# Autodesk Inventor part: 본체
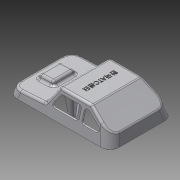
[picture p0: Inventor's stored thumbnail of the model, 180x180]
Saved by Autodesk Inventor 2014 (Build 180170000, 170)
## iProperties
Created: 2015-05
Part Number: 본체
Material: ABS 플라스틱
Document SubType Name: Modeling
Designer: Administrator
Density: 1.06 g/cm^3
Appearance: 매끄러움 - 흰색
Mass: 32.7557 g
Surface Area: 310.511 cm^2
Volume: 30.9016 cm^3
Author: Administrator
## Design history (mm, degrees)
sketch "스케치1"
  geometry: L1 (-61, -38)-(61, -38); L2 (61, -38)-(61, 38); L3 (61, 38)-(-61, 38); L4 (-61, 38)-(-61, -38); L5 (-61, -38)-(61, 38); L6 (61, -38)-(-61, 38); 1 further point
  constraints: 12 end point, 2 midpoint, 2 parallel, 1 horizontal, 1 perpendicular
  dimensions: "d0" = 122 distance of L3.end L2.end; "d1" = 76 distance of L2.end L1.end
extrude "돌출1" new body sketch "스케치1" distance "d2" = 30; taper "d3" = -15 deg
sketch "스케치3"
  geometry: L1 (-31, 30)-(-61, 30); L2 (-61, 30)-(-61, 10); L3 (-61, 10)-(-31, 30); L4 (52.962, 30)-(-52.962, 30) reference; L5 (-61, 0)-(61, 0) reference; 1 further point
  constraints: 6 end point, 1 collinear, 1 horizontal, 1 perpendicular, 1 point on line
  dimensions: "d4" = 30 distance from line of L2 L1.start; "d5" = 20 distance from line of L2.end L1
extrude "돌출2" cut sketch "스케치3" stored distance "d6" = 30; taper "d7" = 0 deg
sketch "스케치4"
  geometry: L1 (61, 8)-(19, 10.201); L2 (19, 10.201)-(6.628, 30); L3 (52.962, 30)-(-31, 30) reference; L4 (61, 8)-(61, 0); L5 (61, 0)-(52.962, 30) reference; L6 (-61, 0)-(61, 0) reference; L7 (6.628, 30)-(61, 30); L8 (61, 30)-(61, 8); 1 further point
  constraints: 10 end point, 2 perpendicular, 1 parallel, 1 point on line
  dimensions: "d8" = 8 distance of L4.end L1.start; "d9" = 3 deg angle of L6 L1; "d10" = 42 horizontal distance of L1.end L1.start; "d11" = 125 deg angle of L1 L2
extrude "돌출3" cut sketch "스케치4" stored distance "d12" = 30; taper "d13" = 0 deg
fillet "모깎기1" dims "d14" = 12
fillet "모깎기2" dims "d15" = 3
sketch "스케치5"
  geometry: L1 (-29.915, 45.985)-(-9.915, 45.985); L2 (-9.915, 45.985)-(-9.915, 19.985); L3 (-9.915, 19.985)-(-29.915, 19.985); L4 (-29.915, 19.985)-(-29.915, 45.985); L5 (-40.915, 59.394)-(-40.915, 6.577) reference; 2 further points
  constraints: 8 end point, 2 parallel, 1 horizontal, 1 horizontal alignment, 1 midpoint, 1 perpendicular
  dimensions: "d16" = 11 distance between parallel lines of L4 L5; "d17" = 20 distance between parallel lines of L2 L4; "d18" = 26 distance between parallel lines of L3 L1
extrude "돌출4" join sketch "스케치5" distance "d19" = 5; taper "d20" = 0 deg
node "작업 평면1"
sketch "스케치6"
  geometry: L1 (-26.409, 0)-(-38, 0) reference; L2 (38, 0)-(26.409, 0) reference; L3 (-25, 0)-(-17, 0); L4 (-14, 0)-(-6, 0); L5 (6, 0)-(14, 0); L6 (17, 0)-(25, 0); A1 r 4 centre (-10, 0) between (-6, 0) and (-14, 0); A2 r 4 centre (-21, 0) between (-17, 0) and (-25, 0); A3 r 4 centre (10, 0) between (14, 0) and (6, 0); A4 r 4 centre (21, 0) between (25, 0) and (17, 0); 1 further point
  constraints: 8 end point, 8 point on circle, 4 centre point, 4 horizontal alignment, 9 other
  dimensions: "d24" = 8 diameter of A1; "d25" = 8 diameter of A2; "d26" = 8 diameter of A3; "d27" = 8 diameter of A4; "d28" = 10 distance of point (0, 0) A1.centre; "d29" = 20 distance of A3.centre A1.centre; "d30" = 11 distance of A1.centre A2.centre; "d31" = 11 distance of A3.centre A4.centre
feature "쉘1" dims "d32" = 2
extrude "돌출5" join sketch "스케치6" stored distance "d33" = 5; taper "d34" = 0 deg
sketch "스케치7"
  geometry: L1 (-58.929, -26.27)-(-58.929, 26.27) reference; L2 (-49.27, 35.929)-(49.27, 35.929) reference; L3 (58.929, 26.27)-(58.929, -26.27) reference; L4 (49.27, -35.929)-(-49.27, -35.929) reference; L5 (49.27, 36.929)-(-49.27, 36.929); L6 (-59.929, 26.27)-(-59.929, -26.27); L7 (-49.27, -36.929)-(49.27, -36.929); L8 (59.929, -26.27)-(59.929, 26.27); 5 further points; 4 other entities
  constraints: 8 end point, 7 parallel, 16 other
  dimensions: "d35" = 1 distance between parallel lines of L2 L5
extrude "돌출6" join sketch "스케치7" distance "d36" = 1; taper "d37" = 0 deg
sketch "스케치8"
  geometry: L1 (4.965, 30)-(-30.092, 30) reference; L2 (18.172, 11.526)-(7.51, 28.59) reference; L3 (-31.756, 29.496)-(-46.213, 19.858) reference; L4 (13.23, 10)-(3.857, 25); L5 (3.857, 25)-(-20.77, 25); L6 (-20.77, 25)-(-20.77, 10); L7 (13.23, 10)-(-20.77, 10); L8 (-23.986, 25)-(-29.486, 25); L9 (-29.486, 25)-(-51.986, 10); L10 (-51.986, 10)-(-23.986, 10); L11 (-23.986, 10)-(-23.986, 25); 1 further point
  constraints: 16 end point, 5 parallel, 3 perpendicular
  dimensions: "d38" = 5 distance between parallel lines of L4 L2; "d39" = 5 distance between parallel lines of L5 L1; "d40" = 34 distance from line of L6 L4.start; "d41" = 15 distance between parallel lines of L7 L5; "d42" = 5 distance between parallel lines of L8 L1; "d43" = 5 distance between parallel lines of L3 L9; "d44" = 15 distance between parallel lines of L10 L8; "d45" = 28 distance from line of L11 L9.end
extrude "돌출7" cut sketch "스케치8" stored distance "d46" = 1; taper "d47" = 0 deg
fillet "모깎기5" dims "d48" = 3
fillet "모깎기6" dims "d49" = 3
sketch "스케치9"
  geometry: C1 r 3 at (0, -22); C2 r 3 at (0, 22); C3 r 3 at (40, 0); C4 r 3 at (-40, 0); 1 further point
  constraints: 4 centre point, 2 horizontal alignment, 2 vertical alignment
  dimensions: "d50" = 6 diameter of C1; "d51" = 6 diameter of C2; "d52" = 6 diameter of C3; "d53" = 6 diameter of C4; "d54" = 40 distance of point (0, 0) C4.centre; "d55" = 40 distance of point (0, 0) C3.centre; "d56" = 44 distance of C2.centre C1.centre; "d57" = 22 distance of C2.centre point (0, 0)
extrude "돌출8" join sketch "스케치9" stored distance "d58" = 2; taper "d59" = 2 deg
node "작업 평면2"
sketch "스케치10"
  geometry: L1 (5, -21)-(-5, -21); L2 (-5, -21)-(-5, -23); L3 (-5, -23)-(5, -23); L4 (5, -23)-(5, -21); L5 (5, -21)-(-5, -23); L6 (-5, -21)-(5, -23); L7 (-35, 1)-(-45, 1); L8 (-45, 1)-(-45, -1); L9 (-45, -1)-(-35, -1); L10 (-35, -1)-(-35, 1); L11 (-35, 1)-(-45, -1); L12 (-45, 1)-(-35, -1); L13 (5, 23)-(-5, 23); L14 (-5, 23)-(-5, 21); L15 (-5, 21)-(5, 21); L16 (5, 21)-(5, 23); L17 (5, 23)-(-5, 21); L18 (-5, 23)-(5, 21); L19 (45, 1)-(35, 1); L20 (35, 1)-(35, -1); L21 (35, -1)-(45, -1); L22 (45, -1)-(45, 1); L23 (45, 1)-(35, -1); L24 (35, 1)-(45, -1); C1 r 3 at (0, -22) reference; C2 r 3 at (-40, 0) reference; C3 r 3 at (0, 22) reference; C4 r 3 at (40, 0) reference; 1 further point
  constraints: 48 end point, 8 midpoint, 8 parallel, 4 horizontal, 4 perpendicular
  dimensions: "d61" = 10 distance of L3.end L2.end; "d62" = 2 distance of L2.end L1.end; "d63" = 10 distance of L9.end L8.end; "d64" = 2 distance of L8.end L7.end; "d65" = 10 distance of L15.end L14.end; "d66" = 2 distance of L14.end L13.end; "d67" = 10 distance of L21.end L20.end; "d68" = 2 distance of L20.end L19.end
extrude "돌출9" join sketch "스케치10" stored distance "d69" = 2; taper "d70" = 2.5 deg
sketch "스케치11"
  geometry: L1 (-35, 2)-(-33.969, 25.617) reference; L2 (-45, 2)-(-45.69, 17.803) reference; L3 (-45.103, 18.194)-(-30.646, 27.832) reference; L4 (-30.092, 28)-(4.965, 28) reference; L5 (-55.687, 11.138)-(-45.103, 18.194) reference; L6 (-37.098, 2)-(-35, 2) reference; L7 (-45, 2)-(-42.902, 2) reference; L8 (-35, 2)-(-30.426, 27.943); L9 (-40, 32.999)-(-40, -19.284); L10 (-43, 0)-(-37, 0) reference; L11 (-45, 2)-(-47.566, 16.552); L12 (33.718, 14.437)-(47.699, 13.704) reference; L13 (47.832, 8.69)-(56.649, 8.228) reference; L14 (35, 2)-(34.546, 12.39) reference; L15 (45, 2)-(45.429, 11.82) reference; L16 (35, 2)-(37.098, 2) reference; L17 (42.902, 2)-(45, 2) reference; L18 (-44.549, 17.621)-(-49.27, 0) reference; L19 (49.27, 0)-(-49.27, 0) reference; L20 (49.27, 0)-(47.675, 5.953) reference; L21 (47.675, 5.953)-(20.403, 7.382) reference; L22 (15.628, 10.195)-(4.965, 27.259) reference; L23 (4.965, 27.259)-(-30.092, 27.259) reference; L24 (-30.092, 27.259)-(-44.549, 17.621) reference; L25 (-43.742, 15.496)-(-30.242, 24.496) reference; L26 (-28.578, 25)-(-26.986, 25) reference; L27 (-23.986, 22)-(-23.986, 13) reference; L28 (-26.986, 10)-(-42.078, 10) reference; L29 (7.818, 10)-(-17.77, 10) reference; L30 (-20.77, 13)-(-20.77, 22) reference; L31 (-17.77, 25)-(2.194, 25) reference; L32 (4.738, 23.59)-(10.362, 14.59) reference; L33 (37, 0)-(36.93, 2) reference; L34 (43, 0)-(43.07, 2) reference; L35 (40, 14.107)-(40, -7.314); L36 (35, 2)-(32.823, 14.348); L37 (45, 2)-(47.07, 13.737); L38 (33.613, 12.439)-(47.594, 11.707) reference; A1 r 1 centre (-30.092, 27) between (-30.092, 28) and (-30.646, 27.832) reference; A2 r 3 centre (33.561, 11.441) between (33.718, 14.437) and (30.633, 12.095) reference; A3 r 3 centre (27.706, 12.749) between (27.549, 9.753) and (30.633, 12.095) reference; A4 r 3 centre (47.542, 10.708) between (50.522, 11.053) and (47.699, 13.704) reference; A5 r 3 centre (53.502, 11.397) between (50.522, 11.053) and (53.345, 8.401) reference; A6 r 6 centre (20.717, 13.374) between (15.628, 10.195) and (20.403, 7.382) reference; A7 r 3 centre (-42.078, 13) between (-43.742, 15.496) and (-42.078, 10) reference; A8 r 3 centre (-28.578, 22) between (-28.578, 25) and (-30.242, 24.496) reference; A9 r 3 centre (-26.986, 22) between (-23.986, 22) and (-26.986, 25) reference; A10 r 3 centre (-26.986, 13) between (-26.986, 10) and (-23.986, 13) reference; A11 r 3 centre (-17.77, 13) between (-20.77, 13) and (-17.77, 10) reference; A12 r 3 centre (-17.77, 22) between (-17.77, 25) and (-20.77, 22) reference; A13 r 3 centre (2.194, 22) between (4.738, 23.59) and (2.194, 25) reference; A14 r 3 centre (7.818, 13) between (7.818, 10) and (10.362, 14.59) reference; A15 r 1 centre (33.561, 11.441) between (33.613, 12.439) and (32.585, 11.659) reference; 2 further points
  constraints: 12 end point, 4 point on line, 2 perpendicular, 2 point on circle, 1 midpoint
  dimensions: "d71" = 10 deg angle of L8 L9; "d72" = 10 deg angle of L9 L11; "d73" = 40 distance from line of L35 point (0, 0); "d74" = 10 deg angle of L35 L36; "d75" = 10 deg angle of L35 L37
  node "투영된 루프3"
extrude "돌출10" join sketch "스케치11" stored distance "d76" = 2; taper "d77" = 0 deg
extrude "돌출11" join sketch "스케치11" stored distance "d78" = 2; taper "d79" = 0 deg
node "작업 평면3"
sketch "스케치12"
  geometry: L1 (-30.092, 28)-(4.965, 28) reference; L2 (-5, 2)-(-6.135, 28) reference; L3 (5, 2)-(6.095, 27.079) reference; L4 (5.813, 27.53)-(16.476, 10.466) reference; L5 (2.902, 2)-(5, 2) reference; L6 (-5, 2)-(-2.902, 2) reference; L7 (5, 2)-(8.69, 22.927); L8 (-5, 2)-(-9.585, 28); L9 (0, 0)-(0, 28)
  constraints: 6 end point, 3 point on line, 1 perpendicular
  dimensions: "d81" = 10 deg angle of L9 L8; "d82" = 10 deg angle of L9 L7
extrude "돌출12" join sketch "스케치12" stored distance "d83" = 2; taper "d84" = 0 deg
extrude "돌출13" join sketch "스케치12" stored distance "d85" = 2; taper "d86" = 0 deg
sketch "스케치13"
  geometry: C1 r 3 at (0, 0) reference; C2 r 3 at (40, -22) reference; C3 r 3 at (0, -44) reference; C4 r 3 at (-40, -22) reference; 5 further points
  constraints: 4 coincident
hole "구멍1" sketch "스케치13" at (0, 0), (40, -22), (0, -44), (-40, -22) diameter "d87" = 3.242; stored, may be unused: countersink angle "d91" = 90 deg, drill point angle "d93" = 118 deg; dims "d88" = 9, "d89" = 4, "d90" = 2, "d92" = 11
chamfer "모따기1" distance "d94" = 1; stored, may be unused: second distance "d95" = 2, angle "d96" = 45 deg
sketch "스케치14"
  geometry: L1 (61, -26.409)-(61, 26.409) reference; 2 further points
  constraints: 1 horizontal alignment, 1 other
  dimensions: "d97" = 50 distance from line of point (11, 0) L1
feature "엠보싱1" sketch "스케치14" dims "d98" = 0.5, "d99" = 0
sketch "스케치15"
  geometry: L1 (30.722, 14.594)-(50.695, 13.547) reference; L2 (50.433, 8.554)-(50.695, 13.547) reference; L3 (30.461, 9.601)-(30.722, 14.594) reference; L4 (47.832, 8.69)-(20.56, 10.119) reference; L5 (47.832, 8.69)-(56.649, 8.228) reference; L6 (50.433, 8.554)-(48.878, 13.642); L7 (30.461, 9.601)-(32.54, 14.498); L8 (48.878, 13.642)-(50.695, 13.547); L9 (50.433, 8.554)-(50.695, 13.547); L10 (32.595, 14.496)-(30.722, 14.594); L11 (30.722, 14.594)-(30.461, 9.601); 1 further point
  constraints: 12 end point, 3 collinear, 3 point on line, 1 perpendicular
  dimensions: "d100" = 110 deg angle of L5 L6; "d101" = 110 deg angle of L7 L4
extrude "돌출14" cut sketch "스케치15" stored distance "d102" = 10; taper "d103" = 0 deg
fillet "모깎기7" dims "d104" = 3
fillet "모깎기8" dims "d105" = 3
fillet "모깎기9" dims "d106" = 3
fillet "모깎기10" dims "d107" = 3
fillet "모깎기11" dims "d108" = 3
node "솔리드1"
mirror "대칭2"
node "투영된 루프1"
node "투영된 루프2"
node "투영된 루프4"
node "투영된 루프5"
node "투영된 루프6"
other parameters: "d23" = -63, "d60" = 2, "d80" = 22
